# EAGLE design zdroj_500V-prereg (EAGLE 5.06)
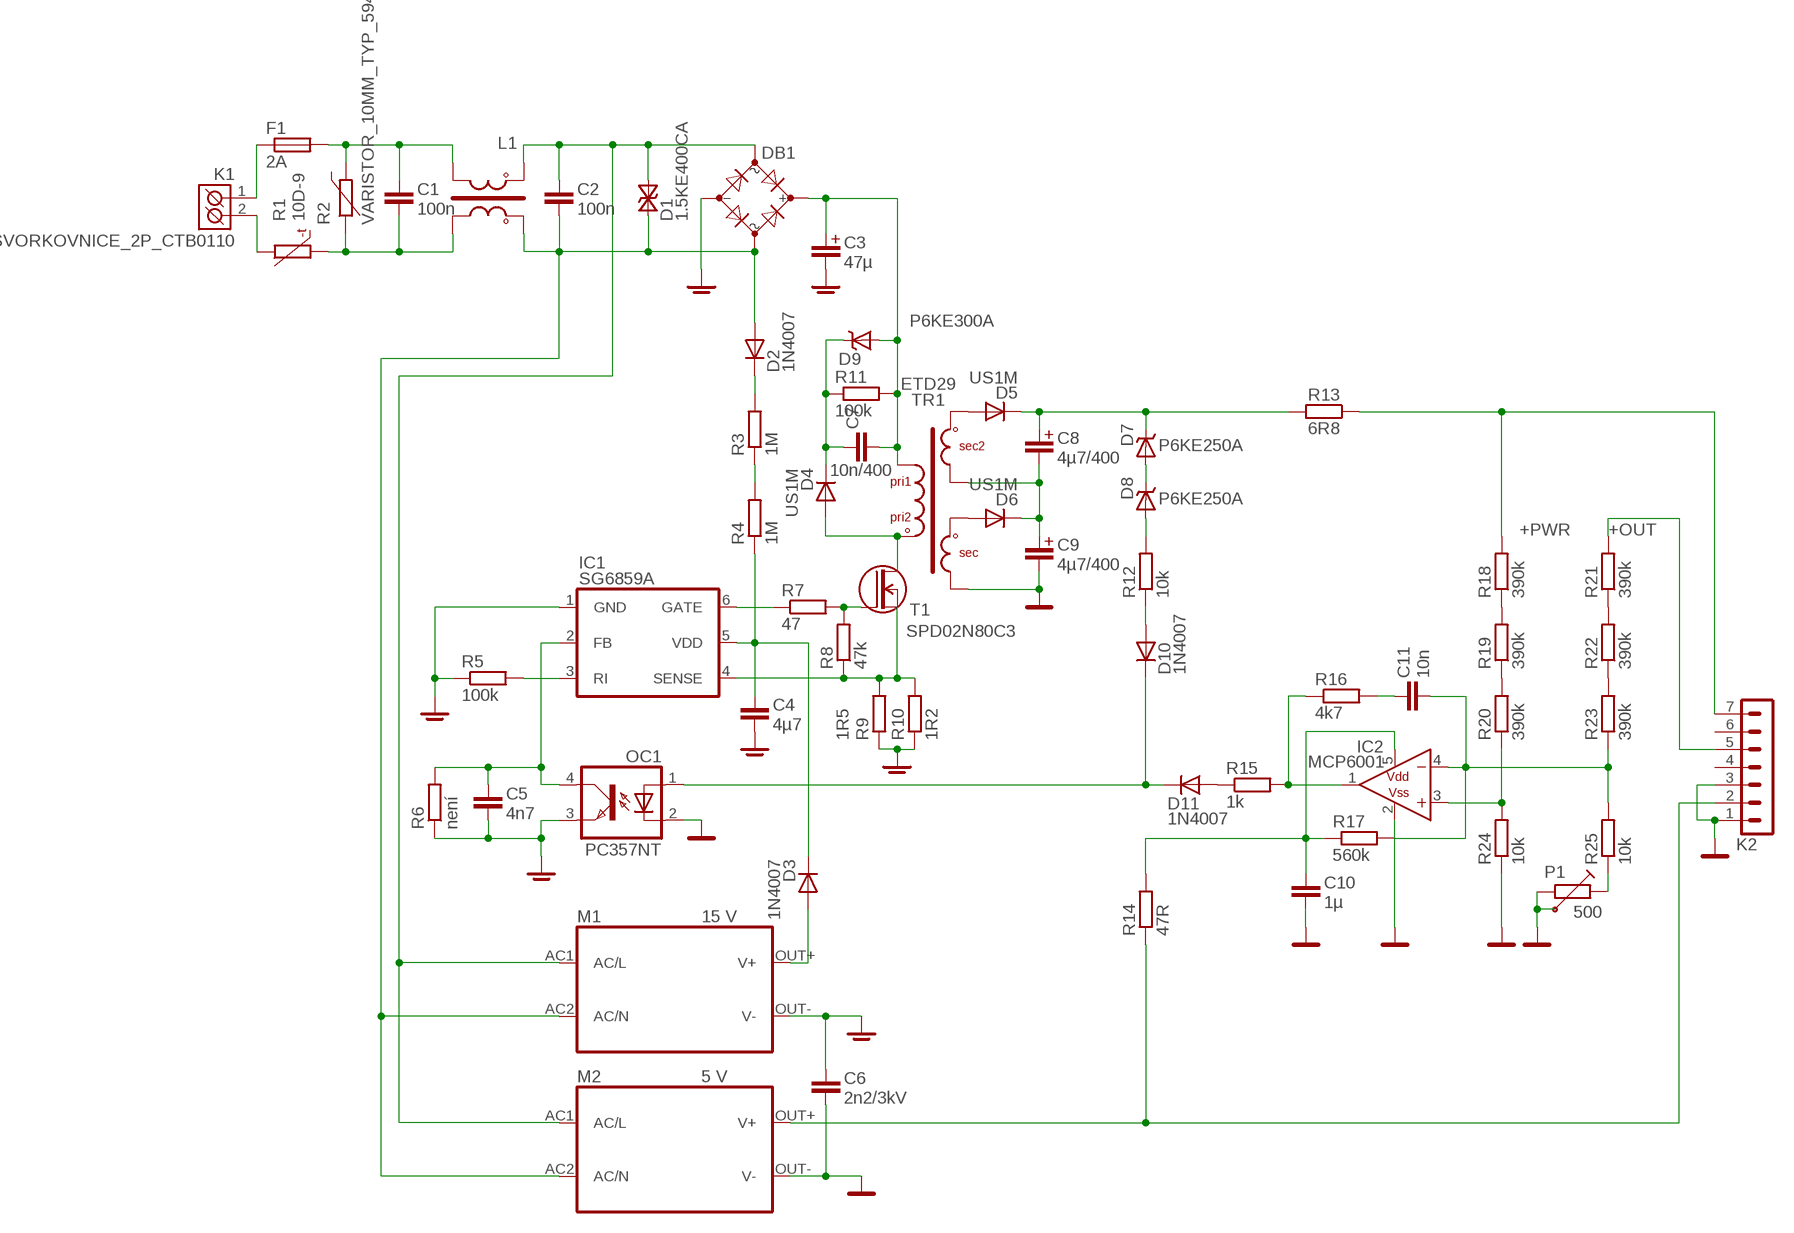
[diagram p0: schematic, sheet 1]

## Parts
C1  100n  C_CFAC100N  [CFAC100N]
C2  100n  C_CFAC100N  [CFAC100N]
C3  47µ  C_ELYT_7.5-18  [CEL_7.5-18]
C4  4µ7  CSMD1206_KEMET_REFLOW  [C1206K]
C5  4n7  CSMD0805_KEMET_REFLOW  [C0805K]
C6  2n2/3kV  C_KER_RM10_14MM  [C_KER_RM10_14MM]
C7  10n/400  C_5-7X3  [C5-7X3]
C8  4µ7/400  C_ELYT_5-10  [CEL_5-10]
C9  4µ7/400  C_ELYT_5-10  [CEL_5-10]
C10  1µ  CSMD0805_KEMET_REFLOW  [C0805K]
C11  10n  CSMD0805_KEMET_REFLOW  [C0805K]
D1  1.5KE400CA  TRANSIL_BI_1.5KE  [DO201-15_BIDIR]
D2  1N4007  DIODASMA  [SMA-DO214AC]
D3  1N4007  DIODASMA  [SMA-DO214AC]
D4  US1M  DIODASMA(B)  [SMA(B)]
D5  US1M  DIODASMA(B)  [SMA(B)]
D6  US1M  DIODASMA(B)  [SMA(B)]
D7  P6KE250A  TRANSIL_DO15-10  [DO15-10]
D8  P6KE250A  TRANSIL_DO15-10  [DO15-10]
D9  P6KE300A  TRANSIL_DO15-10  [DO15-10]
D10  1N4007  DIODASMA  [SMA-DO214AC]
D11  1N4007  DIODASMA  [SMA-DO214AC]
DB1  DIODA-MUSTEK_DIL-SMD  [DM-DIL-SMD]
F1  2A  POJISTKA_MST-MSF  [POJISTKA_MST_MSF]
IC1  SG6859ATZ  [SOT23-6]
IC2  MCP6001  MCP6L01_  [SOT23-5]
K1  SVORKOVNICE_2P_CTB0110  [CTB0110/2]
K2  KONZ-07PSH02  [PSH02-07]
L1  EMI_FILTR_WE_40418  [EMI_FILTR_WE_7448640418]
M1  15 V  MODUL_AC/DC_SANMIN_3W  [AC/DC_SANMIN_3W]
M2  5 V  MODUL_AC/DC_SANMIN_3W  [AC/DC_SANMIN_3W]
OC1  PC357NT  OPTOCOUPLER_4PIN_FLAT_2.54  [SMD_MINI-FLAT]
P1  500  R-TRIMRPT6V  [PT6V]
R1  10D-9  TERMISTOR_INRUSH_10MM  [TERMISTOR_INRUSH_10MM]
R2  VARISTOR_10MM_TYP_594  [VARISTOR_594]
R3  1M  REZISTOR_SMD1206_KEMET_REFLOW  [C1206K]
R4  1M  REZISTOR_SMD1206_KEMET_REFLOW  [C1206K]
R5  100k  REZISTOR_SMD0805_KEMET_REFLOW  [C0805K]
R6  není  REZISTOR_SMD0805_KEMET_REFLOW  [C0805K]
R7  47  REZISTOR_SMD0805_KEMET_REFLOW  [C0805K]
R8  47k  REZISTOR_SMD0805_KEMET_REFLOW  [C0805K]
R9  1R5  REZISTOR_SMD1206_KEMET_REFLOW  [C1206K]
R10  1R2  REZISTOR_SMD1206_KEMET_REFLOW  [C1206K]
R11  100k  REZISTOR_411-5  [0411-5]
R12  10k  REZISTOR_SMD1206_KEMET_REFLOW  [C1206K]
R13  6R8  REZISTOR_411-5  [0411-5]
R14  47R  REZISTOR_SMD0805_KEMET_REFLOW  [C0805K]
R15  1k  REZISTOR_SMD0805_KEMET_REFLOW  [C0805K]
R16  4k7  REZISTOR_SMD0805_KEMET_REFLOW  [C0805K]
R17  560k  REZISTOR_SMD0805_KEMET_REFLOW  [C0805K]
R18  390k  REZISTOR_SMD1206_KEMET_REFLOW  [C1206K]
R19  390k  REZISTOR_SMD1206_KEMET_REFLOW  [C1206K]
R20  390k  REZISTOR_SMD1206_KEMET_REFLOW  [C1206K]
R21  390k  REZISTOR_SMD1206_KEMET_REFLOW  [C1206K]
R22  390k  REZISTOR_SMD1206_KEMET_REFLOW  [C1206K]
R23  390k  REZISTOR_SMD1206_KEMET_REFLOW  [C1206K]
R24  10k  REZISTOR_SMD0805_KEMET_REFLOW  [C0805K]
R25  10k  REZISTOR_SMD0805_KEMET_REFLOW  [C0805K]
T1  SPD02N80C3  T_NFETTO252_DPAK  [TO252-R]
TR1  ETD29  TRAFO_ETD29_REGULOVANY_ZDROJ  [KOSTRA_ETD29_2S_RM5(REAL_SIZE)]

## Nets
+OUT: K2.5 R21.2
+PWR: K2.7 R13.1 R18.2
DRAIN: D4.A T1.4(D) TR1.6-PS(PS)
GND: C6.2 C9.- C10.2 IC2.2(VSS) K2.1 K2.3 M2.OUT-(V-) OC1.2(C) P1.1 P1.3 R24.1 TR1.9-S1E(S1E)
GNDA: C3.- C4.2 C5.2 C6.1 DB1.- IC1.1(GND) M1.OUT-(V-) OC1.3(EMIT) R5.1 R6.1 R9.1 R10.1
N$1: C11.1 R16.2
N$2: C11.2 IC2.4(-IN) R17.2 R23.1 R25.2
N$3: F1.F1 K1.1(K1)
N$4: K2.2 M2.OUT+(V+) R14.1
N$5: C1.P$1 F1.F2 L1.P$2 R2.F2
N$6: C1.P$2 L1.P$3 R1.2 R2.F1
N$7: C2.P$1 D1.A DB1.S1(AC1) L1.P$1 M1.AC1(AC/L) M2.AC1(AC/L)
N$8: C2.P$2 D1.K D2.A DB1.S2(AC2) L1.P$4 M1.AC2(AC/N) M2.AC2(AC/N)
N$9: C3.+ C7.2 D9.A DB1.+ R11.2 TR1.4-PE(PE)
N$11: IC1.6(GATE) R7.1
N$12: D5.A TR1.13-S2S(S2S)
N$13: D6.A TR1.8-S1S(S1S)
N$14: C10.1 IC2.5(VDD) R14.2 R17.1
N$15: C8.- C9.+ D6.K TR1.14-S2E(S2E)
N$16: IC1.3(RI) R5.2
N$17: R22.1 R23.2
N$18: R7.2 R8.2 T1.1(G)
N$19: IC1.4(SENSE) R8.1 R9.2 R10.2 T1.3(S)
N$20: C5.1 IC1.2(FB) OC1.4(COL) R6.2
N$21: R21.1 R22.2
N$22: C4.1 D3.K IC1.5(VDD) R4.1
N$23: IC2.3(+IN) R20.1 R24.2
N$24: P1.2 R25.1
N$25: IC2.1(OUT) R15.2 R16.1
N$26: D2.K R3.2
N$27: D11.A R15.1
N$28: R3.1 R4.2
N$29: D3.A M1.OUT+(V+)
N$30: K1.2(K2) R1.1
N$31: C8.+ D5.K D7.K R13.2
N$32: C7.1 D4.K D9.K R11.1
N$33: D7.A D8.K
N$34: D8.A R12.2
N$35: D10.K D11.K OC1.1(A)
N$36: D10.A R12.1
N$39: R19.1 R20.2
N$40: R18.1 R19.2
Unconnected: K2.4 K2.6 TR1.5-PM(PM)

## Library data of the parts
C1 C2 C4-C7 C10 C11 = #bcs7d:C: Kondenzatory, keramicke a foliove
C3 C8 C9 = #bcs7d:C_ELYT: Kondenzatory, elektrolyticke
D1 = #bcs7d:TRANSIL_BI: Transil obousmerny
D2-D6 D10 D11 = #bcs7d:DIODA
D7-D9 = #bcs7d:TRANSIL: Transient voltage suppressor - TRANSIL
DB1 = #bcs7d:DIODA-MUSTEK
F1 = #bcs7d:POJISTKA_: Pojistka
IC1 = #bcs-ic1:SG6859A: Green Mode Flyback PWM Controller
IC2 = #bcs-ic1:MCP6L01: 5 pin OA MCP6L01
K1 = #bcs_pinhead:SVORKOVNICE_2P_: Svorkovnice 2 piny
K2 = #bcs_pinhead:KONZ-07: Konektory se zamkem - vidlice - 7pin
L1 = #bcs_special:EMI_FILTR: Common mode choke
M1 M2 = #bcs_special:MODUL_AC/DC: AC/DC 3W SANMIN
OC1 = #bcs-ic1:OPTOCOUPLER_4PIN_: TEXAS INSTRUMENTS OPTO COUPLER
P1 = #bcs7d:R-TRIMR
R1 = #bcs7d:TERMISTOR
R2 = #bcs7d:VARISTOR
R3-R25 = #bcs7d:REZISTOR_
T1 = #bcs7d:T_NFET: N-FET
TR1 = #bcs_special:TRAFO_ETD29_REGULOVANY_ZDROJ: Trafo pro predregulátor ke spínanému zdroji

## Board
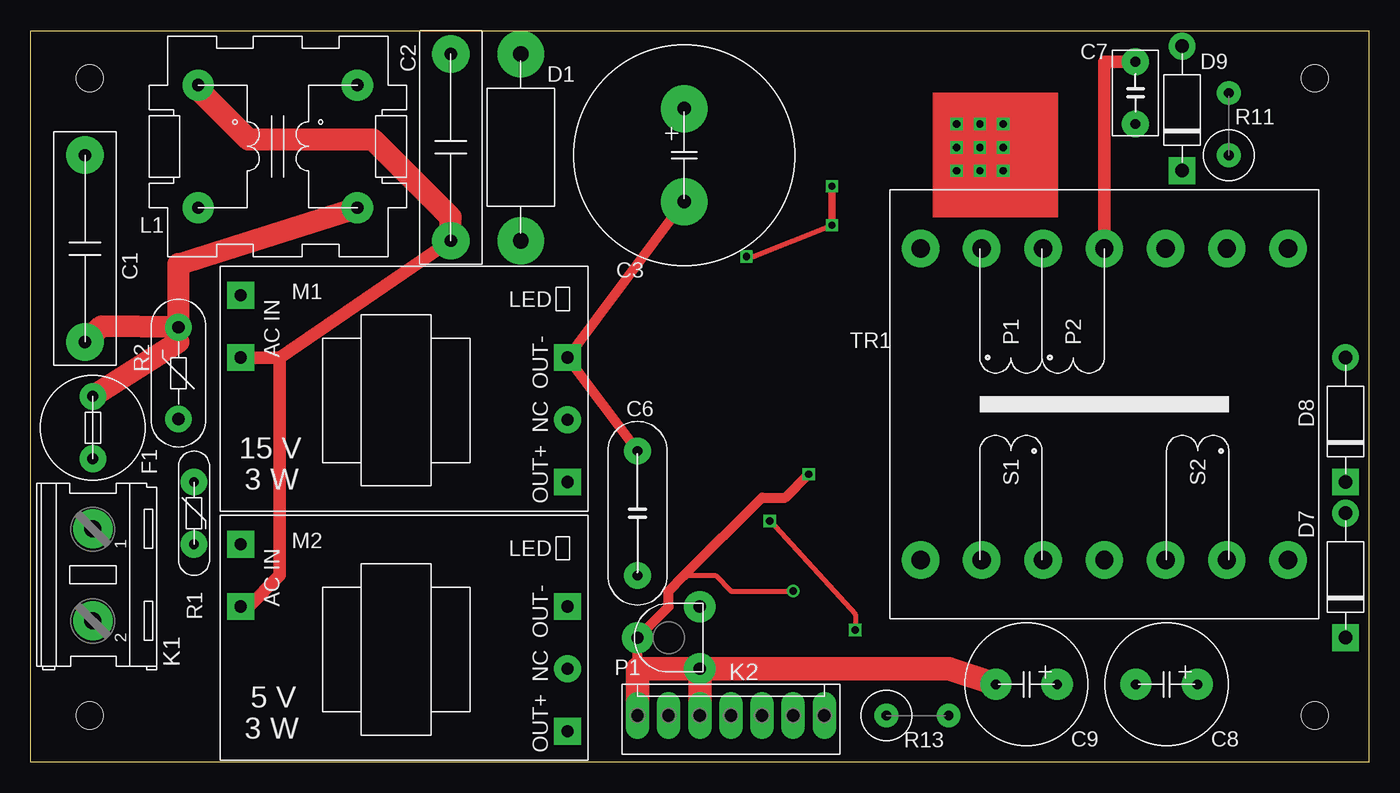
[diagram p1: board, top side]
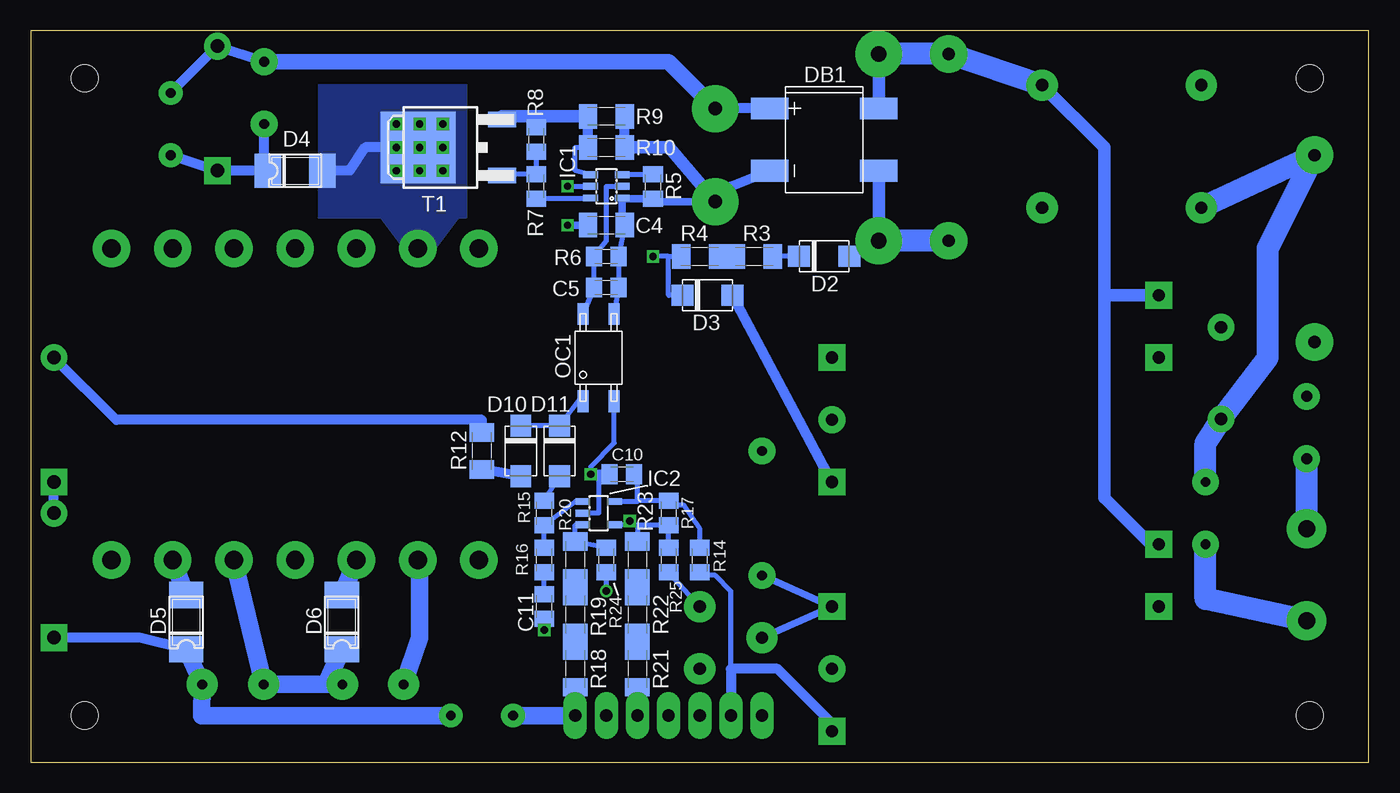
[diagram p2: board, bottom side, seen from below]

Size 109.22 x 59.69 mm. Coordinates in mm from the lower left corner, seen from the top.
Outline: 0,0 0,59.69 109.22,59.69 109.22,0 0,0
Copper layers (1*16): Top 0.035mm / dielectric 1.5mm / Bottom 0.035mm
Design rules "default": minimum track width 10mil, minimum drill 24mil, track to track 8mil, track to pad 8mil, pad to pad 8mil, via to via 8mil, smd to smd 8mil, copper to edge 40mil, drill to drill 8mil, minimum pad ring 10mil, minimum via ring 8mil, stop-mask expansion 4mil, vias tented up to drill 0mil, thermal gap 10mil
Holes 2.2 mm at 4.81,3.81 104.81,3.81 104.81,55.81 4.81,55.81

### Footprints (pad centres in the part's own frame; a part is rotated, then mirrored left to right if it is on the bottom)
CFAC100N = drill 1 pad 3.048 round: P$1 -7.62,0; P$2 7.62,0
CEL_7.5-18 = drill 1.1 pad 3.81 round: + -3.794,0; - 3.794,0
C1206K = smd 1.5 x 2: 1 -1.5,0; 2 1.5,0
C0805K = smd 1.3 x 1.6: 1 -1,0; 2 1,0
C_KER_RM10_14MM = drill 0.8 pad 2.184 round: 1 -5.08,0; 2 5.08,0
C5-7X3 = drill 0.8 pad 2.184 round: 1 -2.54,0; 2 2.54,0
CEL_5-10 = drill 0.8 pad 2.54 round: + -2.5,0; - 2.5,0
DO201-15_BIDIR = drill 1.3 pad 3.81 round: A 7.62,0; K -7.62,0
SMA-DO214AC = smd 1.8 x 1.7: A 2.05,0; K -2.05,0
SMA(B) = smd 2.159 x 2.794: A 2.21,0; K -2.21,0
DO15-10 = drill 1.1 pad 2.184 round: A 5.08,0 | drill 1.1 pad 2.184 square: K -5.08,0
DM-DIL-SMD = smd 1.778 x 3.048: + -2.54,-4.445; - 2.54,-4.445; S1 -2.54,4.445; S2 2.54,4.445
POJISTKA_MST_MSF = drill 0.9 pad 2.184 round: F1 2.54,0; F2 -2.54,0
SOT23-6 = smd 0.55 x 1.2: 1 -0.95,-1.3; 2 0,-1.3; 3 0.95,-1.3; 4 0.95,1.3; 5 0,1.3; 6 -0.95,1.3
SOT23-5 = smd 0.55 x 1.2: 1 -0.95,-1.3; 2 0,-1.3; 3 0.95,-1.3; 4 0.95,1.3; 5 -0.95,1.3
CTB0110/2 = drill 1.4 pad 3.2 round: 1 0,0; 2 7.5,0
PSH02-07 = drill 1 pad 1.93 long: 1 -7.62,0; 2 -5.08,0; 3 -2.54,0; 4 0,0; 5 2.54,0; 6 5.08,0; 7 7.62,0
EMI_FILTR_WE_7448640418 = drill 1 pad 2.54 round: P$1 0,0; P$2 0,10; P$3 13,10; P$4 13,0
AC/DC_SANMIN_3W = drill 1 pad 2.184 square: AC1 -13.335,7.62; AC2 -13.335,2.54; OUT+ 13.335,-7.62; OUT- 13.335,2.54 | drill 1 pad 2.184 round: NC 13.335,-2.54
SMD_MINI-FLAT = smd 0.914 x 1.778: 1 -1.27,-3.556; 2 1.27,-3.556; 3 1.27,3.556; 4 -1.27,3.556
PT6V = drill 1 pad 2.54 round: 1 -2.54,-2.54; 2 2.54,-2.54; 3 0,2.54
TERMISTOR_INRUSH_10MM = drill 0.8 pad 2.184 round: 1 -2.54,0; 2 2.54,0
VARISTOR_594 = drill 1 pad 2.184 round: F1 3.75,0; F2 -3.75,0
0411-5 = drill 0.8 pad 1.93 round: 1 -2.54,0; 2 2.54,0
TO252-R = smd 1.27 x 2.286: 1 -2.286,-5.461; 3 2.286,-5.461 | smd 5.842 x 6.096: 4 0,1.397
KOSTRA_ETD29_2S_RM5(REAL_SIZE) = drill 1.5 pad 3.048 round: 1 -12.7,15; 2 -12.7,10; 3 -12.7,5; 4-PE -12.7,0; 5-PM -12.7,-5; 6-PS -12.7,-10; 7 -12.7,-15; 8-S1S 12.7,-5; 9-S1E 12.7,-10; 10 12.7,-15; 11 12.7,0; 12 12.7,15; 13-S2S 12.7,10; 14-S2E 12.7,5

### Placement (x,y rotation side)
C1  4.45,41.91 90 top
C2  34.29,50.16 270 top
C3  53.34,49.53 270 top
C4  62.23,43.81 0 bottom
C5  62.23,38.73 0 bottom
C6  49.53,20.32 270 top
C7  90.17,54.61 90 top
C8  92.71,6.35 180 top
C9  81.28,6.35 180 top
C10  60.96,23.5 180 bottom
C11  67.31,12.7 270 bottom
D1  40.01,50.16 90 top
D2  44.45,41.27 0 bottom
D3  53.98,38.1 0 bottom
D4  87.63,48.26 0 bottom
D5  96.52,11.43 90 bottom
D6  83.82,11.43 90 bottom
D7  107.31,15.24 90 top
D8  107.31,27.94 90 top
D9  93.98,53.34 90 top
D10  69.22,25.4 270 bottom
D11  66.04,25.4 270 bottom
DB1  44.45,50.8 270 bottom
F1  5.08,27.3 270 top
IC1  62.23,46.99 90 bottom
IC2  62.87,20.32 270 bottom
K1  5.08,19.05 270 top
K2  57.15,3.81 0 top
L1  26.67,55.24 180 top
M1  30.48,30.48 0 top
M2  30.48,10.16 0 top
OC1  62.87,33.02 0 bottom
P1  52.07,10.16 90 top
R1  13.34,20.32 90 top
R2  12.06,31.75 270 top
R3  50.16,41.27 0 bottom
R4  54.61,41.27 0 bottom
R5  58.42,46.99 90 bottom
R6  62.23,41.27 180 bottom
R7  67.94,46.99 90 bottom
R8  67.94,50.8 270 bottom
R9  62.23,52.7 180 bottom
R10  62.23,50.16 180 bottom
R11  97.79,52.07 90 top
R12  72.39,25.4 90 bottom
R13  72.39,3.81 0 top
R14  54.61,16.51 90 bottom
R15  67.31,20.32 270 bottom
R16  67.31,16.51 270 bottom
R17  57.15,20.32 270 bottom
R18  64.77,7.62 270 bottom
R19  64.77,12.06 270 bottom
R20  64.77,16.51 270 bottom
R21  59.69,7.62 270 bottom
R22  59.69,12.06 270 bottom
R23  59.69,16.51 270 bottom
R24  62.23,16.51 90 bottom
R25  57.15,16.51 90 bottom
T1  76.2,50.16 90 bottom
TR1  87.63,29.21 270 top

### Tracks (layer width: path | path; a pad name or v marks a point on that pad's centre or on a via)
+OUT
  Bottom 0.406: K2.5 R21.2
+PWR
  Bottom 0.406: K2.7 R18.2
  Bottom 1.422: K2.7 R13.1
DRAIN  (via drill 0.6)
  Bottom 0.813: T1.4 v79.38,50.16 81.92,50.16 83.19,48.26 D4.A
  pour Bottom (no thermals): 73.66,44.45 73.66,55.24 85.72,55.24 85.72,44.45 80.64,44.45 78.74,41.91 76.2,41.91 74.3,44.45
GND  (via drill 0.6)
  Top 0.406: v62.23,13.97 57.15,13.97 55.88,15.24 53.34,15.24
  Top 0.813: 49.53,7.62 P1.3 52.07,12.7 52.07,13.97 53.34,15.24 59.69,21.59 61.59,21.59 v63.5,23.5
  Top 1.93: P1.1 74.93,7.62 C9.- | P1.1 K2.3 | P1.1 49.53,7.62 K2.1
  Bottom 0.406: v62.23,13.97 R24.1 | IC2.2 62.87,20.32 62.87,23.23 C10.2 | OC1.2 61.59,26.04 63.5,24.13 v63.5,23.5
  Bottom 0.61: P1.3 M2.OUT- C6.2
  Bottom 0.813: v63.5,23.5 C10.2
  Bottom 1.422: TR1.9-S1E 77.47,15.24 77.47,10.16 C9.-
GNDA
  Top 0.813: C6.1 M1.OUT- C3.-
  Bottom 0.406: OC1.3 C5.2 R6.1 C4.2 60.73,44.45 60.96,44.45 | IC1.1 60.93,45.99 60.96,45.99 | R5.1 58.42,45.74 58.42,45.72
  Bottom 0.61: R5.1 60.96,45.99 60.96,44.45 | C3.- 58.42,45.74
  Bottom 0.813: DB1.- 52.07,46.99 C3.- | R10.1 R9.1
  Bottom 1.016: R10.1 57.13,50.16 C3.-
N$1
  Bottom 0.406: C11.1 R16.2
N$2  (via drill 0.6)
  Top 0.406: v60.33,19.68 67.31,12.06 v67.31,10.79
  Bottom 0.406: R25.2 R17.2 57.18,19.35 59.69,19.35 | 59.69,19.35 IC2.4 | v67.31,10.79 C11.2 | 59.69,19.35 R23.1 | v60.33,19.68 60.33,19.35 59.69,19.35
N$3
  Bottom 1.778: K1.1 F1.F1
N$4
  Bottom 0.406: R14.1 54.34,15.24 53.34,15.24 52.07,13.97 52.07,7.62
  Bottom 0.813: M2.OUT+ 43.81,3.17 48.26,7.62 52.07,7.62 K2.2
N$5
  Top 1.016: 12.06,34.29 R2.F2
  Top 1.778: F1.F2 12.06,34.29 | L1.P$2 12.06,40.64 R2.F2 5.78,35.56 C1.P$1
N$6
  Bottom 1.016: 12.06,27.94 R2.F1
  Bottom 1.778: R1.2 13.34,26.04 12.06,27.94 | R2.F1 8.26,33.02 8.26,41.91 C1.P$2 L1.P$3
N$7
  Bottom 1.016: D1.A DB1.S1 | M2.AC1 17.78,17.78 21.59,21.59 21.59,38.1 | 21.59,38.1 M1.AC1 | L1.P$1 21.59,50.16 21.59,38.1
  Bottom 1.778: D1.A C2.P$1 L1.P$1
N$8
  Top 1.016: M2.AC2 17.78,12.7 20.32,15.24 20.32,33.02 | 20.32,33.02 C2.P$2 | 20.32,33.02 M1.AC2
  Top 1.778: C2.P$2 34.29,44.45 27.94,50.8 17.78,50.8 13.67,54.91 L1.P$4
  Bottom 0.813: D1.K D2.A
  Bottom 1.016: D1.K DB1.S2
  Bottom 1.778: C2.P$2 D1.K
N$9
  Top 1.016: C7.2 87.63,57.15 TR1.4-PE
  Bottom 0.813: DB1.+ 52.07,53.34 C3.+ | C7.2 D9.A R11.2
  Bottom 1.27: C3.+ 57.15,57.15 C7.2
N$10  (via drill 0.6)
  other vias: 75.56,52.07
N$11
  Bottom 0.406: IC1.6 63.53,45.99 R7.1
N$12
  Bottom 1.422: D5.A TR1.13-S2S
N$13
  Bottom 1.422: D6.A TR1.8-S1S
N$14
  Bottom 0.406: C10.1 59.69,23.5 59.69,21.32 | IC2.5 59.69,21.27 59.69,21.32 | 59.69,21.32 R17.1 57.15,20.95 55.88,20.95 54.61,19.05 R14.2
N$15
  Bottom 1.422: C9.+ 85.09,6.35 | 85.09,6.35 C8.- TR1.14-S2E | 85.09,6.35 D6.K
N$16
  Bottom 0.406: IC1.3 60.93,47.99 R5.2
N$17
  Bottom 0.406: R22.1 R23.2
N$18
  Bottom 0.406: R8.2 R7.2 70.74,47.99
  Bottom 0.61: 70.74,47.99 T1.1
N$19
  Bottom 0.406: IC1.4 64.77,48.26 64.77,50.16 R10.2
  Bottom 0.61: 67.94,52.7 R8.1 | 70.74,52.7 T1.3
  Bottom 0.813: R10.2 R9.2
  Bottom 1.016: R9.2 67.94,52.7 70.74,52.7
N$20
  Bottom 0.406: OC1.4 C5.1 R6.2 62.23,42.55 62.23,46.99 IC1.2
N$21
  Bottom 0.406: R21.1 R22.2
N$22  (via drill 0.6)
  Top 0.406: v65.41,43.81 59.05,41.27 v58.42,41.27
  Top 0.61: v65.41,43.81 v65.41,46.99
  Bottom 0.406: v65.41,46.99 IC1.5 | 57.15,41.27 R4.1 | 57.15,41.27 57.15,38.1 D3.K | 57.15,41.27 v58.42,41.27
  Bottom 0.61: v65.41,43.81 C4.1
N$23
  Bottom 0.406: IC2.3 64.77,19.37 R20.1 R24.2
N$24
  Bottom 0.406: P1.2 R25.1
N$25
  Bottom 0.406: IC2.1 64.77,21.27 R15.2 R16.1
N$26
  Bottom 0.406: D2.K R3.2
N$27
  Bottom 0.406: R15.1 D11.A
N$28
  Bottom 0.406: R4.2 R3.1
N$29
  Bottom 0.813: M1.OUT+ D3.A
N$30
  Bottom 1.778: K1.2 13.34,13.34 R1.1
N$31
  Bottom 0.813: D7.K 100.33,10.16 D5.K
  Bottom 1.422: D5.K C8.+ 95.25,3.81 R13.2
N$32
  Bottom 0.813: C7.1 90.17,48.26 D4.K D9.K R11.1
N$33
  Bottom 0.813: D7.A D8.K
N$34
  Bottom 0.813: R12.2 72.39,27.94 102.23,27.94 D8.A
N$35
  Bottom 0.406: OC1.1 64.14,29.99 D11.K D10.K
N$36
  Bottom 0.813: D10.A R12.1
N$37  (via drill 0.6)
  other vias: 75.56,50.16
N$38  (via drill 0.6)
  other vias: 75.56,48.26
N$39
  Bottom 0.406: R19.1 R20.2
N$40
  Bottom 0.406: R18.1 R19.2
N$41  (via drill 0.6)
  other vias: 77.47,48.26
N$42  (via drill 0.6)
  other vias: 79.38,48.26
N$43  (via drill 0.6)
  other vias: 77.47,50.16
N$44  (via drill 0.6)
  other vias: 77.47,52.07
N$45  (via drill 0.6)
  other vias: 79.38,52.07
(copper drawn outside any net)
  shapes: Top area x1

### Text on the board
tPlace: 15 V | 5 V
